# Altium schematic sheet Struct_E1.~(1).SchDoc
size 420 x 297 mm; Scale: 1:1; Разраб.: Иванов; Обозначение документа: АБВГ.123456.001 Э3; Пров.: Петров; Утв.: Сидоров; Наименование организации: ОАО "Концерн "МПО-Гидроприбор"; Перв. применение: АБВГ.123456.000; Наименование изделия 1: Плата; Наименование изделия 2: Схема электрическая; Наименование изделия 3: принципиальная; Нач. отд.: Нач. отд.; Фамилия нач. отд.: Сидоров
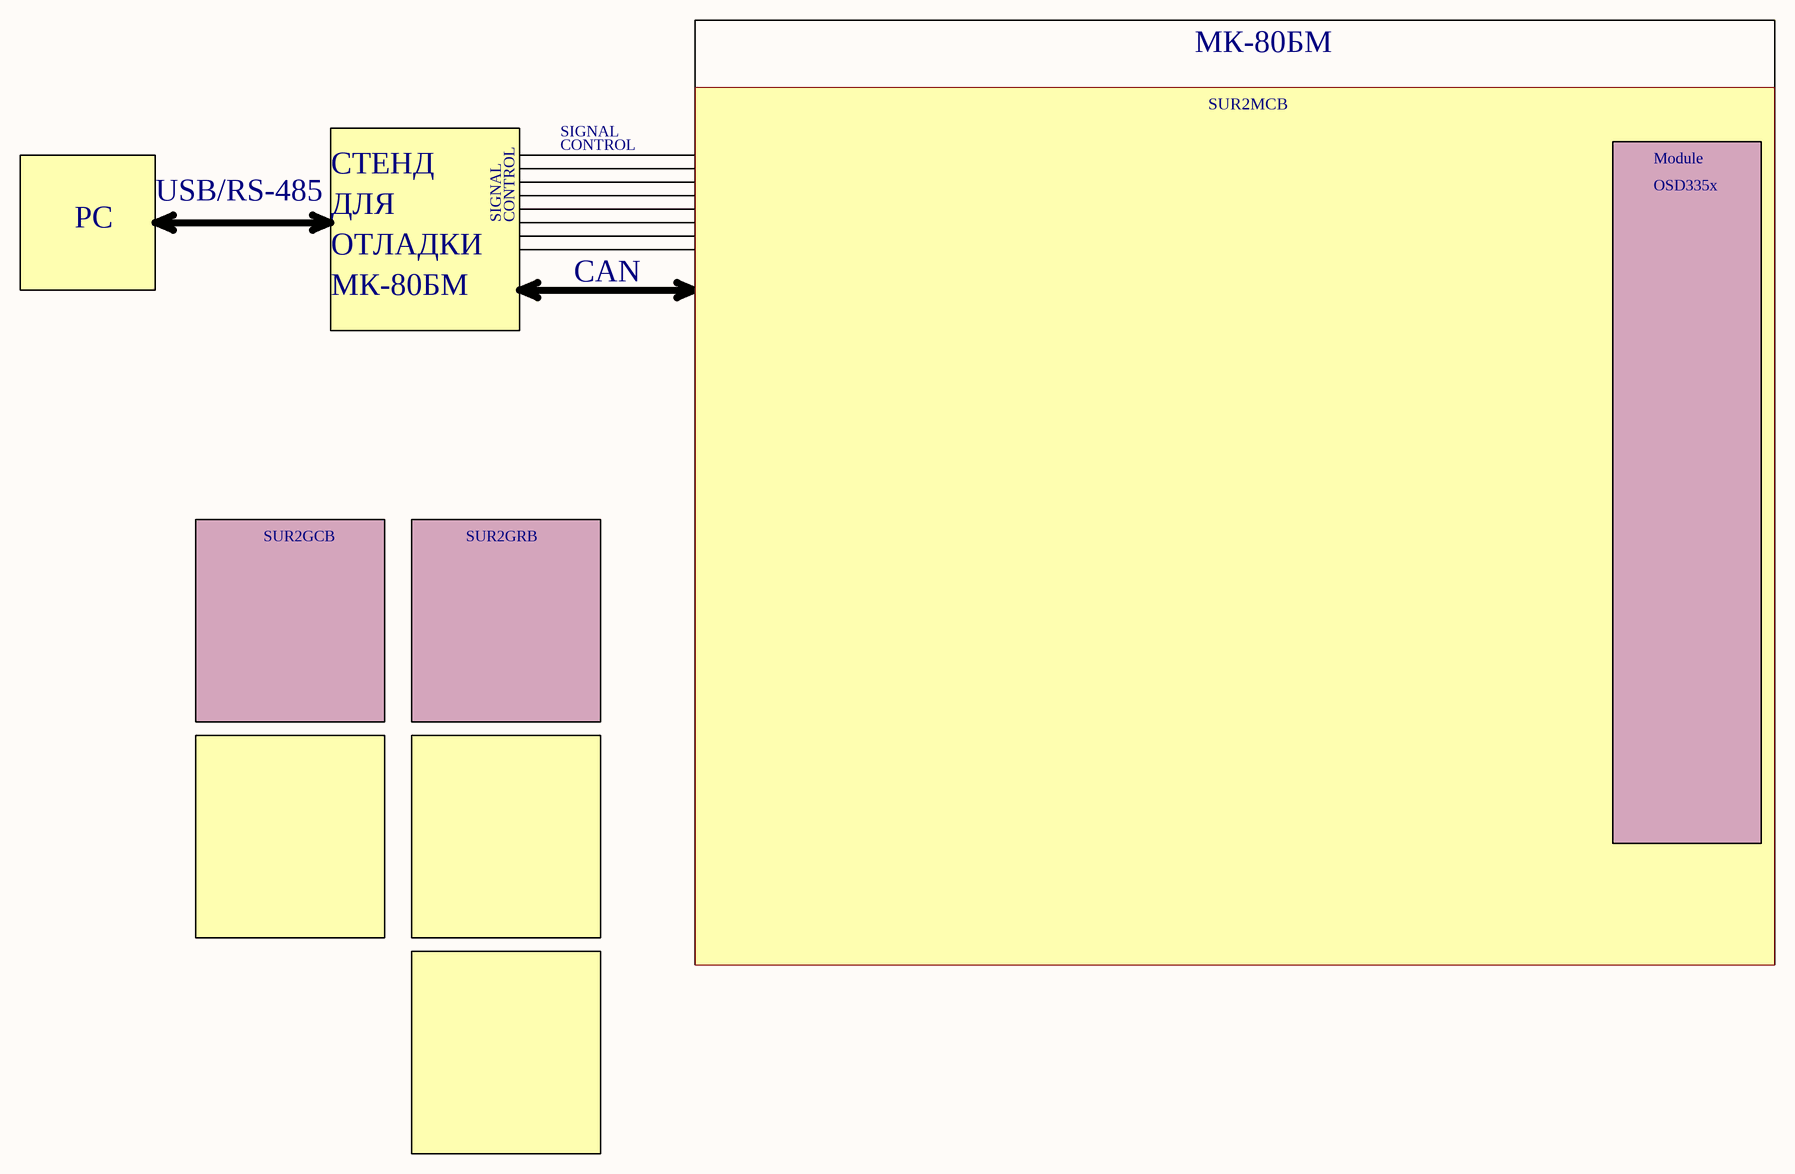
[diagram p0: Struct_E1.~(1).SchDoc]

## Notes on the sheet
- МК-80БМ
- SUR2MCB
- СТЕНД
- SIGNAL
- CONTROL
- Module
- PC
- USB/RS-485
- ДЛЯ
- OSD335x
- ОТЛАДКИ
- CAN
- SUR2GCB
- SUR2GRB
